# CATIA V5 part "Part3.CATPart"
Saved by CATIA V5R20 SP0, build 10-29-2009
Part number: Part3
Bounding box of the stored display mesh (mm): x -47.5 to 47.5, y -47.5 to 47.5, z 0 to 0
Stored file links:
  D:\liandongzhou\Part3.CATPart
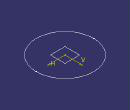
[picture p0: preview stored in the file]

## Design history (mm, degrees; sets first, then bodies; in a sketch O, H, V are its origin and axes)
Set1
  Sketch1 on xy-plane, origin (0, 0, 0), H (1, 0, 0), V (0, 1, 0)
    circle A1 centre (0, 0) radius 47.5
    radius A1 = 47.5
Body1 (main body)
